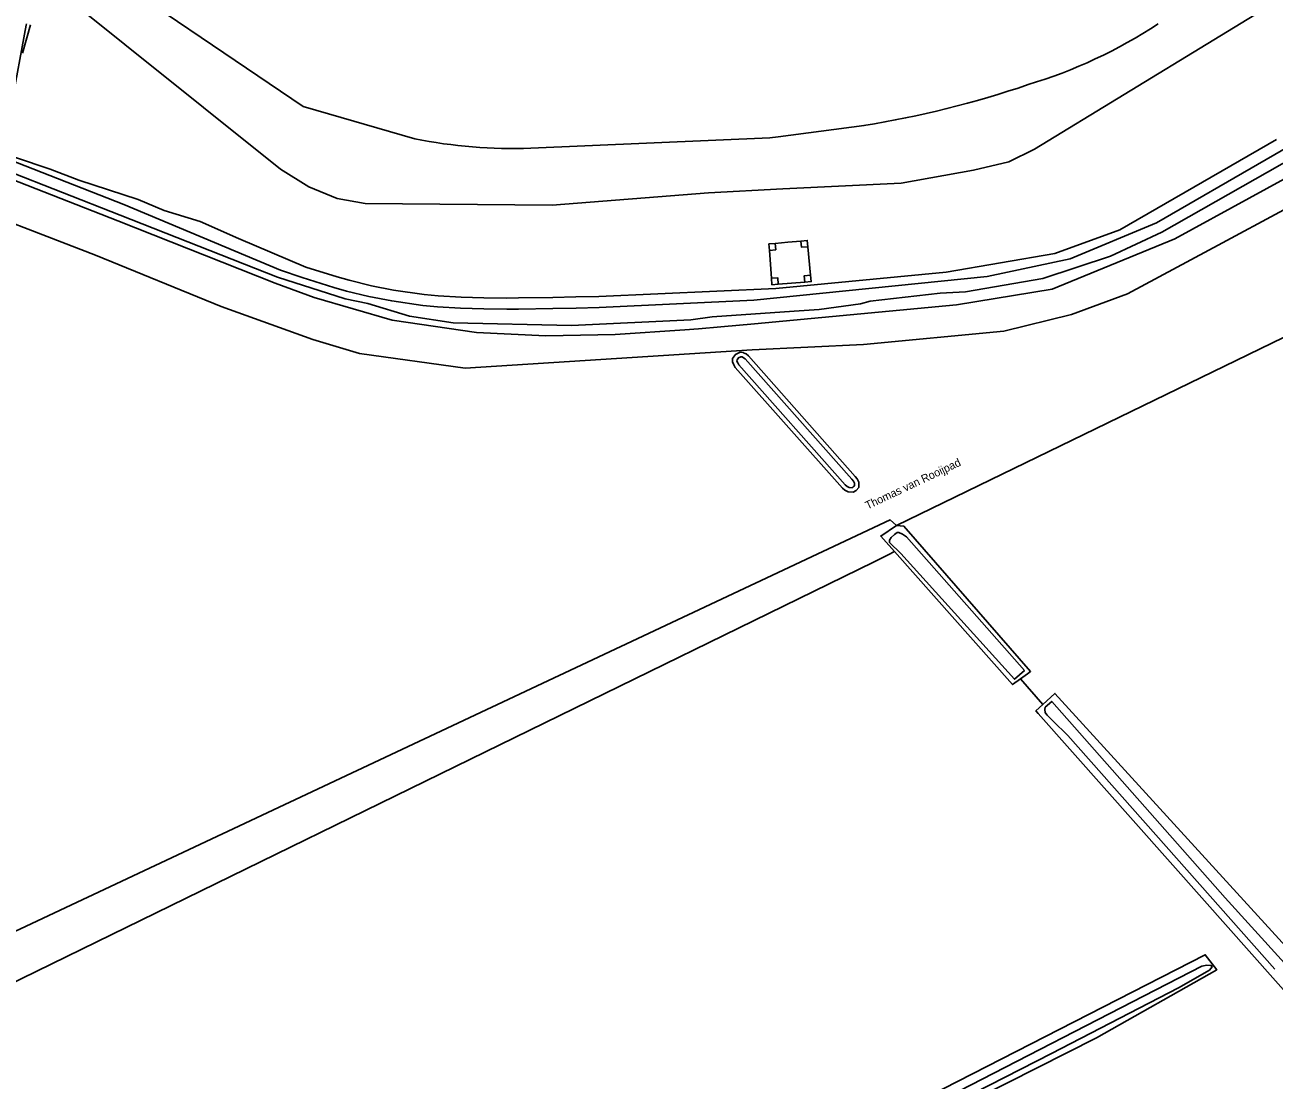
# Model space of a CAD drawing. Extents: x 164494 to 166241, y 382475 to 384494.
# Drawn here: x 165198.1 to 165354.3, y 382727.2 to 382859.1 of the extents above; entities that cross this region are included whole.
import ezdxf

# ---------------------------------------------------------------- set-up
doc = ezdxf.new("R2010")
doc.units = 0
for name, color, linetype in [('IMGEO_Grasland_agrarisch', 7, 'Continuous'), ('IMGEO_Grasland_overig', 7, 'Continuous'), ('IMGEO_Hek', 7, 'Continuous'), ('IMGEO_Hoogspanningsmast', 7, 'Continuous'), ('IMGEO_Loofbos', 7, 'Continuous'), ('IMGEO_Openbare_ruimte_label', 7, 'Continuous'), ('IMGEO_Waterloop', 7, 'Continuous')]:
    doc.layers.add(name, color=color, linetype=linetype)

msp = doc.modelspace()

# ---------------------------------------------------------------- linework, layer by layer
at = {"layer": 'IMGEO_Grasland_agrarisch'}
for points in [[(165300.3, 382801.23), (165300.62, 382800.98), (165300.71, 382800.93), (165301.02, 382800.76), (165301.65, 382800.73), (165302.03, 382800.95), (165302.35, 382801.33), (165302.37, 382801.96), (165302.14, 382802.38), (165301.91, 382802.7), (165288.55, 382817.78), (165288.26, 382818.01), (165288.03, 382818.12), (165287.91, 382818.18), (165287.53, 382818.22), (165286.94, 382817.96), (165286.59, 382817.46), (165286.58, 382817.02), (165286.72, 382816.64), (165286.91, 382816.33), (165300.3, 382801.23)], [(165322.55, 382777.38), (165323.43, 382778.03), (165323.83, 382778.32), (165307.99, 382796.47), (165307.05, 382796.58)], [(165306.81, 382793.31), (165321.58, 382776.67), (165322.55, 382777.38)], [(165322.55, 382777.38), (165325.35, 382774.18)], [(165325.35, 382774.18), (165326.88, 382775.58), (165389.84, 382706.54), (165390.34, 382705.9), (165390.85, 382705.23), (165391.54, 382704.25), (165391.87, 382703.71), (165392.32, 382702.73), (165392.56, 382701.39), (165392.51, 382701.16), (165392.23, 382699.91)], [(165249.54, 382624.64), (165259.71, 382630.25), (165309.39, 382657.69), (165322.04, 382664.7), (165388.32, 382701.46), (165345.24, 382750), (165324.77, 382773.07), (165324.49, 382773.39), (165325.35, 382774.18)], [(165209.86, 382670.66), (165280.13, 382706.24), (165280.34, 382706.35), (165332.05, 382732.53), (165347.1, 382741.03), (165345.65, 382742.9), (165265.64, 382701.97), (165207.89, 382672.93)]]:
    msp.add_lwpolyline(points, dxfattribs=at)
at = {"layer": 'IMGEO_Grasland_overig'}
for points in [[(165188.11, 382843.13), (165209.76, 382834.65), (165229.42, 382826.86), (165234.27, 382825.05), (165244.03, 382822.25), (165254.59, 382820.68), (165263.23, 382820.27), (165271.9, 382820.45), (165280.61, 382821.02), (165282.33, 382821.17), (165285.13, 382821.41), (165289.34, 382821.78), (165314.58, 382824.15), (165326.52, 382826.1), (165341.86, 382832.39), (165369.72, 382847.67), (165382.06, 382855.78), (165383.04, 382857.32)], [(165187.69, 382837.79), (165206.93, 382830.37), (165222.66, 382823.96), (165234.13, 382819.81), (165239.94, 382818.07), (165253.15, 382816.24), (165289.04, 382818.52), (165302.95, 382819.19), (165320.47, 382820.84), (165328.95, 382822.95), (165335.96, 382825.53), (165347.82, 382831.91), (165362.07, 382839.55), (165376.85, 382847.65), (165381.51, 382850.1), (165388.71, 382836.93), (165391.8, 382833.55), (165397.77, 382835.43)]]:
    msp.add_lwpolyline(points, dxfattribs=at)
at = {"layer": 'IMGEO_Hek'}
for points in [[(165201.01, 382864.46), (165204.43, 382868.24), (165232.91, 382848.94), (165246.85, 382844.9)], [(165292.26, 382845.17), (165303.01, 382846.57)], [(165261.35, 382843.72), (165291.25, 382845.04), (165292.26, 382845.17)], [(165307.05, 382796.58), (165395, 382839.26)]]:
    msp.add_lwpolyline(points, dxfattribs=at)
for centre, radius, start, end in [((165305.48, 382911.5), 62.48, 286.7755, 303.2765), ((165282.89, 382971.15), 126.19, 279.1715, 288.7787), ((165259.29, 382908.42), 64.73, 258.9238, 271.8251)]:
    msp.add_arc(centre, radius, start, end, dxfattribs=at)
at = {"layer": 'IMGEO_Hoogspanningsmast'}
for points in [[(165291.91, 382831.83), (165291.12, 382831.76), (165291.18, 382830.96)], [(165291.18, 382830.96), (165291.97, 382831.03), (165291.91, 382831.83)], [(165295.99, 382831.41), (165295.92, 382832.21), (165295.12, 382832.13)], [(165295.12, 382832.13), (165295.2, 382831.34), (165295.99, 382831.41)], [(165296.33, 382827.84), (165295.53, 382827.78), (165295.61, 382826.99)], [(165295.61, 382826.99), (165296.41, 382827.05), (165296.33, 382827.84)], [(165292.29, 382826.73), (165292.23, 382827.53), (165291.43, 382827.47)], [(165291.43, 382827.47), (165291.49, 382826.67), (165292.29, 382826.73)]]:
    msp.add_lwpolyline(points, dxfattribs=at)
at = {"layer": 'IMGEO_Loofbos'}
for points in [[(165369.14, 382871.01), (165324.33, 382843.63), (165321.12, 382842.04), (165316.68, 382840.98), (165307.64, 382839.37), (165292.87, 382838.64), (165283.57, 382838.17), (165264.01, 382836.63), (165240.67, 382836.81), (165237.15, 382837.43), (165233.6, 382838.92), (165230.06, 382841.12), (165201.01, 382864.46)], [(165201.01, 382864.46), (165204.43, 382868.24), (165232.91, 382848.94), (165246.85, 382844.9)], [(165197.82, 382855.6), (165198.84, 382859.15)], [(165261.35, 382843.72), (165291.25, 382845.04), (165292.26, 382845.17), (165303.01, 382846.57)], [(165354.57, 382844.83), (165334.98, 382833.52), (165326.85, 382830.57), (165313.29, 382828.24), (165291.99, 382826.19), (165269.87, 382825.2), (165266.99, 382825.13), (165264.11, 382825.07), (165259.81, 382825.01), (165258.36, 382825), (165255.49, 382825.02), (165252.64, 382825.11), (165249.8, 382825.28), (165248.02, 382825.45), (165244.2, 382826), (165241.43, 382826.54), (165238.67, 382827.22), (165237.15, 382827.64), (165233.23, 382828.88), (165224.82, 382832.45), (165220.05, 382834.58), (165215.52, 382835.96), (165212.27, 382837.3), (165204.85, 382839.72), (165201.3, 382841.1), (165196.93, 382842.55)], [(165291.43, 382827.47), (165291.18, 382830.96)], [(165291.91, 382831.83), (165293.49, 382831.98), (165295.12, 382832.13)], [(165295.99, 382831.41), (165296.33, 382827.84)], [(165295.61, 382826.99), (165293.96, 382826.86), (165292.29, 382826.73)], [(165307.05, 382796.58), (165306.26, 382797.27), (165147.73, 382722.73), (165139.3, 382717.42)], [(165306.81, 382793.31), (165305.45, 382794.84), (165305.1, 382795.25), (165307.05, 382796.58)], [(165164.03, 382723.48), (165304.18, 382791.97), (165306.03, 382792.88), (165306.81, 382793.31)]]:
    msp.add_lwpolyline(points, dxfattribs=at)
for centre, radius, start, end in [((165305.48, 382911.5), 62.48, 286.7755, 303.2765), ((165282.89, 382971.15), 126.19, 279.1715, 288.7787), ((165259.29, 382908.42), 64.73, 258.9238, 271.8251)]:
    msp.add_arc(centre, radius, start, end, dxfattribs=at)
at = {"layer": 'IMGEO_Waterloop'}
for points in [[(165198.34, 382859.26), (165198.29, 382859.1), (165196.39, 382848.96)], [(165195.09, 382842.73), (165210.48, 382836.71), (165230.07, 382828.5), (165232.8, 382827.56), (165236.76, 382826.3), (165238.32, 382825.87), (165241.13, 382825.19), (165243.97, 382824.63), (165247.86, 382824.07), (165249.7, 382823.9), (165252.58, 382823.72), (165255.47, 382823.63), (165258.36, 382823.61), (165259.83, 382823.62), (165264.13, 382823.68), (165267.02, 382823.74), (165269.9, 382823.81), (165289.24, 382824.75), (165318.41, 382827.7), (165328.77, 382829.9), (165339.56, 382834.4), (165366.97, 382850.23)], [(165363.55, 382846.49), (165340.24, 382833.24), (165333.83, 382830.23), (165325.36, 382827.46), (165315.69, 382825.76), (165312.51, 382825.6), (165303.79, 382824.62), (165302.55, 382824.27), (165297.41, 382823.56), (165294.28, 382823.35), (165284.04, 382822.64), (165281.35, 382822.29), (165266.43, 382821.56), (165251.66, 382821.9), (165246.19, 382822.73), (165240.98, 382824.3), (165238.15, 382824.88), (165229.71, 382827.59), (165210.05, 382835.37), (165188.38, 382843.86)], [(165300.67, 382801.63), (165287.36, 382816.66), (165287.22, 382816.89), (165287.13, 382817.11), (165287.14, 382817.27), (165287.31, 382817.52), (165287.62, 382817.66), (165287.76, 382817.64), (165287.96, 382817.54), (165288.16, 382817.38), (165301.48, 382802.35), (165301.68, 382802.09), (165301.8, 382801.84), (165301.8, 382801.54), (165301.67, 382801.38), (165301.51, 382801.29), (165301.17, 382801.31), (165300.92, 382801.44), (165300.67, 382801.63)], [(165308.3, 382795.13), (165307.83, 382795.46), (165307.37, 382795.68), (165307.14, 382795.68), (165306.82, 382795.44), (165306.41, 382795.06), (165306.19, 382794.71), (165306.21, 382794.44), (165307.63, 382793.08), (165321.83, 382777.35), (165323.06, 382778.45), (165308.3, 382795.13)], [(165354.34, 382741.08), (165328.5, 382770.3), (165326.61, 382772.16), (165326.1, 382772.65), (165325.89, 382772.85), (165325.72, 382773.05), (165325.65, 382773.18), (165325.61, 382773.55), (165325.64, 382773.84)], [(165325.64, 382773.84), (165326.48, 382774.57), (165348.17, 382750), (165388.54, 382705.53)], [(165260.26, 382697.93), (165282.62, 382709.37), (165309.1, 382722.9), (165345.24, 382741.47), (165345.87, 382741.61), (165346.28, 382741.57), (165346.42, 382741.56), (165346.51, 382741.39), (165346.18, 382740.99), (165342.3, 382738.78), (165326.46, 382730.57), (165252.44, 382692.77), (165211.51, 382671.99), (165210.67, 382672.35), (165210.67, 382673.27), (165213.45, 382674.84), (165233.49, 382684.53), (165260.26, 382697.93)]]:
    msp.add_lwpolyline(points, dxfattribs=at)

# ---------------------------------------------------------------- texts
at = {"layer": 'IMGEO_Openbare_ruimte_label'}
msp.add_text('Thomas van Rooijpad', height=1, rotation=25.2835, dxfattribs=at).set_placement((165303.45, 382798.55))

doc.saveas('drawing.dxf')
